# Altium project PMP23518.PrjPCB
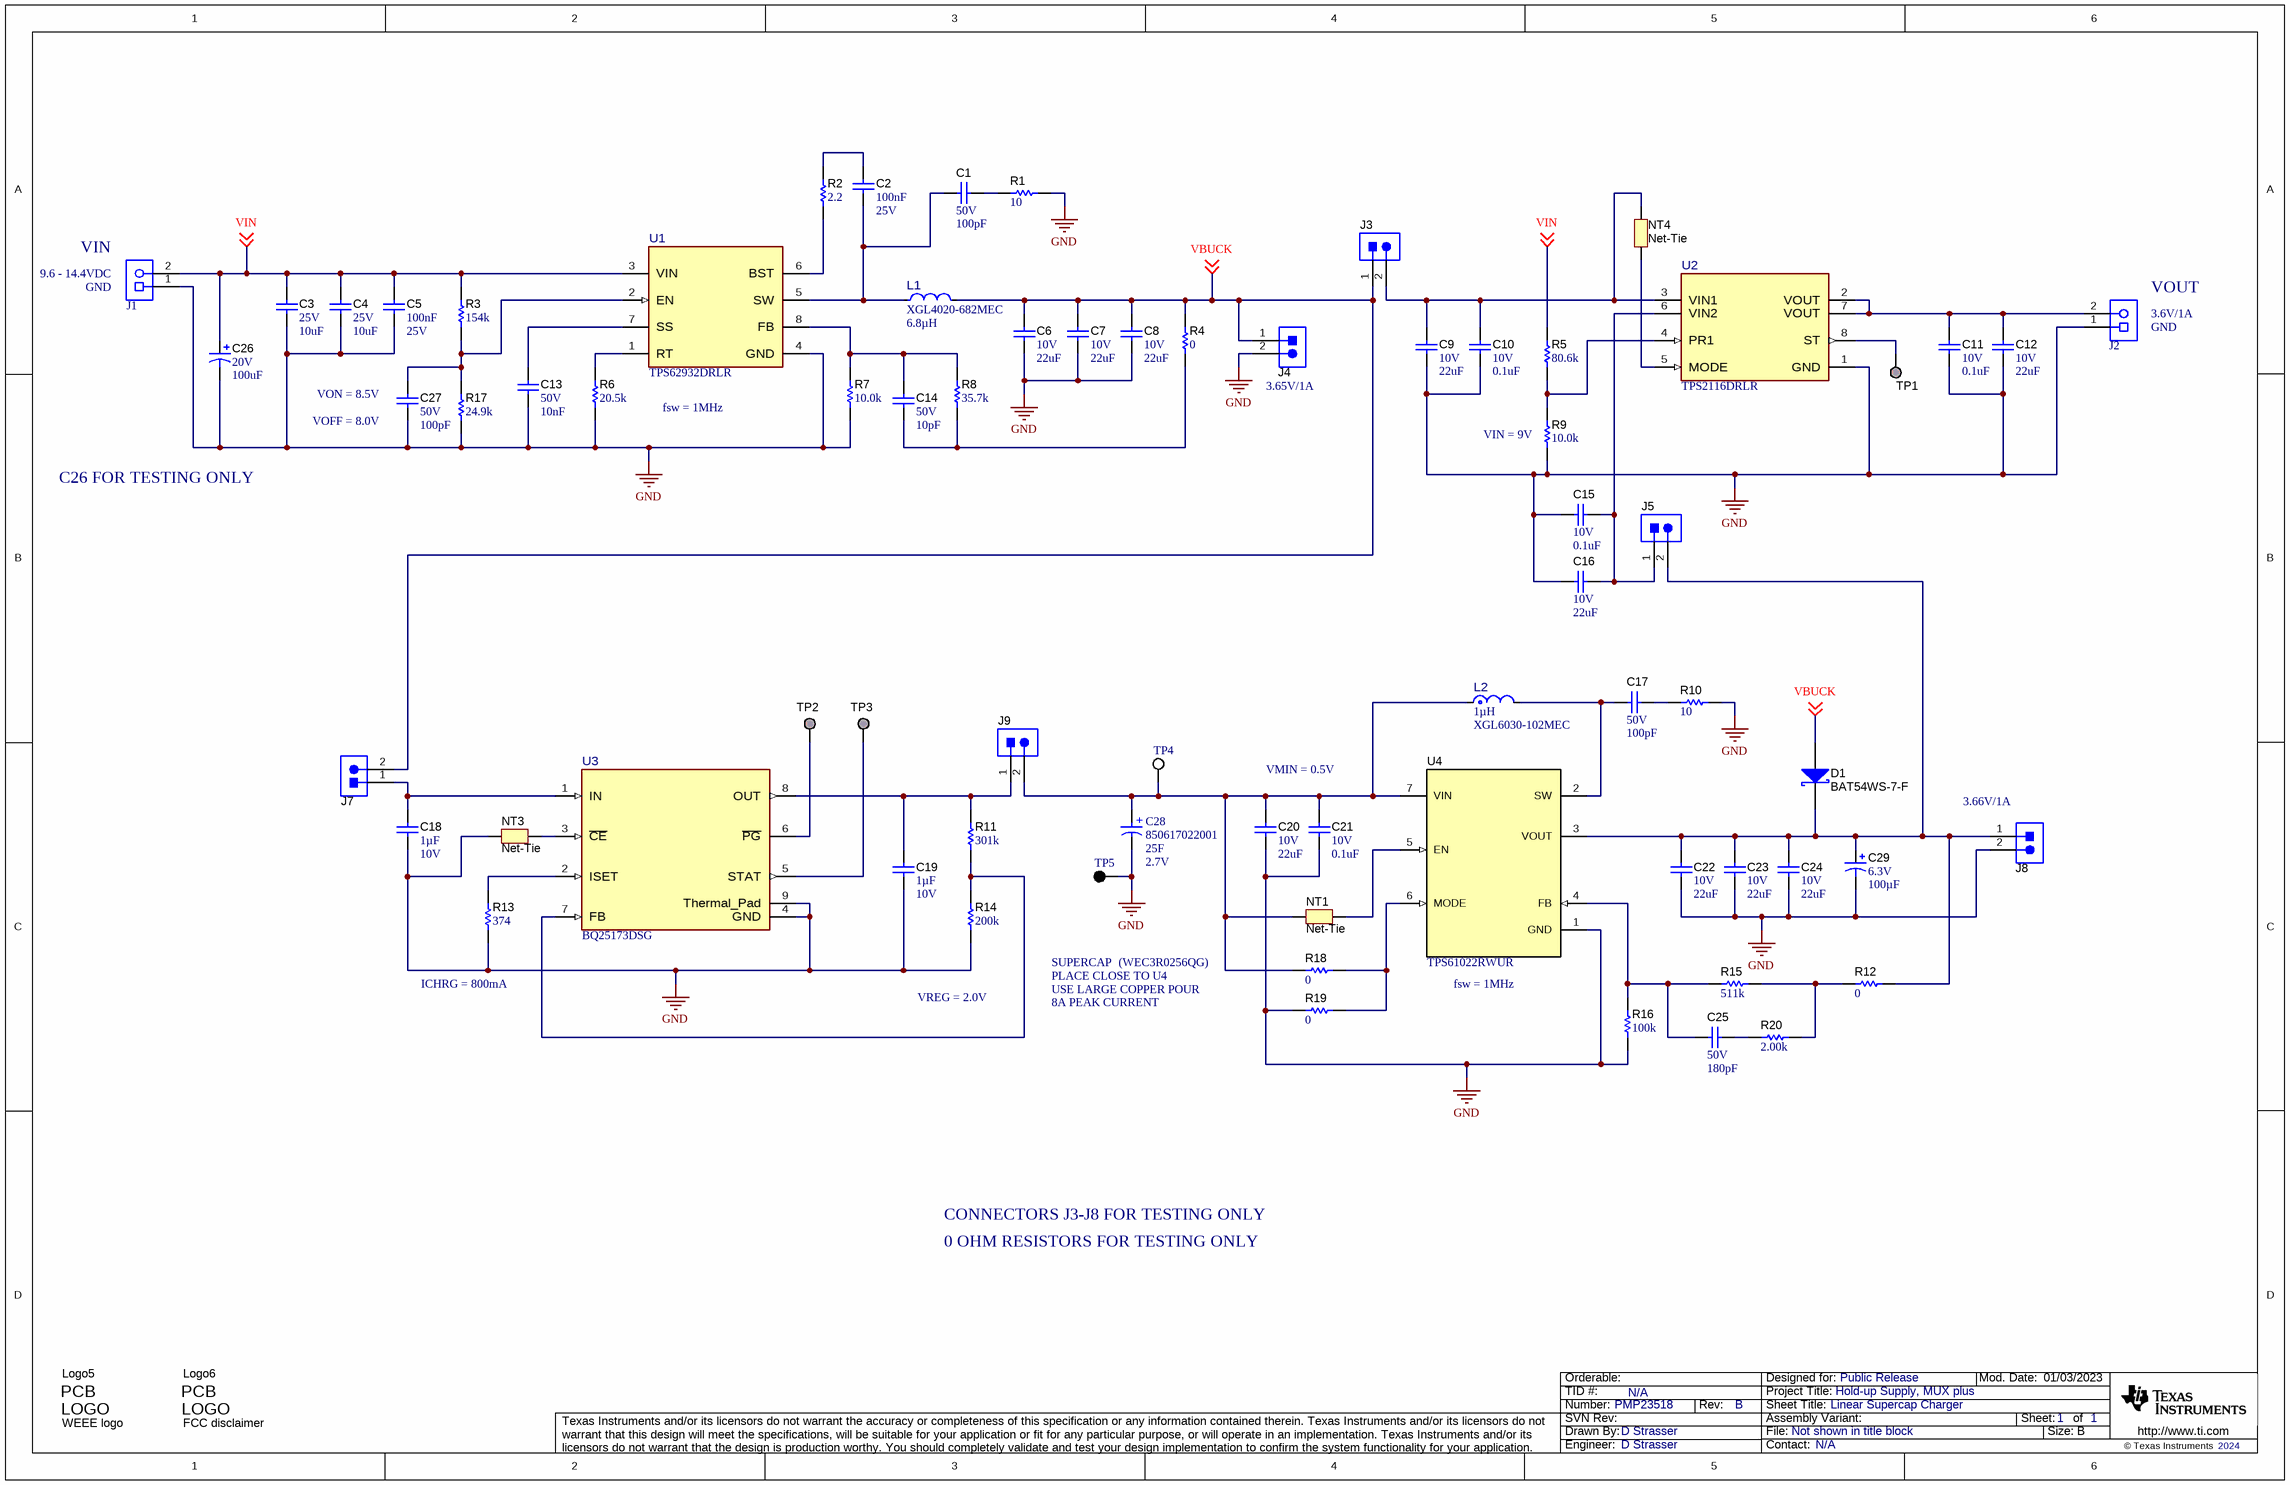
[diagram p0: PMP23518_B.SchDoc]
CopyrightYear: 2024; PCB_Layout: D Strasser; PCB_Rev: B; PRJ_Customer: Public Release; PRJ_Engineer: D Strasser; PRJ_Number: PMP23518; PRJ_Title: Hold-up Supply, MUX plus; SCH_Rev: B; TechSupport: N/A; TID: N/A
1 sheet, 74 parts. Net scope: global (net labels, ports and power ports of the same name join across sheets).
Board file: PMP23518_B.PcbDoc

## Sheet PMP23518_B.SchDoc: Linear Supercap Charger
size 431 x 279 mm; Date: Not shown in title block; ApprovedBy: Not shown in title block; CheckedBy: Not shown in title block; Author: Not shown in title block; CompanyName: Not shown in title block; DrawnBy: D Strasser; Engineer: Not shown in title block; Organization: Not shown in title block; Address1: Not shown in title block; Address2: Not shown in title block; Address3: Not shown in title block; Address4: Not shown in title block; DocumentNumber: 1; Revision: Use project parameter SCH_Rev; SheetNumber: 1; SheetTotal: 1; PageSetup: Record=PageOptions¦CenterHorizontal=True¦CenterVertical=True¦PrintScale=1.00¦XCorrection=1.00¦YCorrection=1.00¦PrintKind=0¦BorderSize=5000000¦LeftOffset=0¦BottomOffset=0¦Orientation=2¦PaperLength=1000¦PaperWidth=1000¦Scale=100¦PaperSource=15¦PrintQuality=600¦MediaType=1¦DitherType=10¦PaperKind=Letter¦PrintScaleMode=1

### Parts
C1  VDC_V: 50V  ValueDisplayed: 100pF  [0603]  (hidden comment: 885012006057)
C2  Cap_F: 100nF  VDC_V: 25V  [0603]  (hidden comment: 885012206071)
C3  VDC_V: 25V  ValueDisplayed: 10uF  [1206]  (hidden comment: 885012208069)
C4  VDC_V: 25V  ValueDisplayed: 10uF  [1206]  (hidden comment: 885012208069)
C5  Cap_F: 100nF  VDC_V: 25V  [0603]  (hidden comment: 885012206071)
C6  VDC_V: 10V  ValueDisplayed: 22uF  [0805_HV1]  (hidden comment: GRM21BR61A226ME44L)
C7  VDC_V: 10V  ValueDisplayed: 22uF  [0805_HV1]  (hidden comment: GRM21BR61A226ME44L)
C8  VDC_V: 10V  ValueDisplayed: 22uF  [0805_HV1]  (hidden comment: GRM21BR61A226ME44L)
C9  VDC_V: 10V  ValueDisplayed: 22uF  [0805_HV1]  (hidden comment: GRM21BR61A226ME44L)
C10  VDC_V: 10V  ValueDisplayed: 0.1uF  [0402]  (hidden comment: 885012105010)
C11  VDC_V: 10V  ValueDisplayed: 0.1uF  [0402]  (hidden comment: 885012105010)
C12  VDC_V: 10V  ValueDisplayed: 22uF  [0805_HV1]  (hidden comment: GRM21BR61A226ME44L)
C13  VDC_V: 50V  Cap_F: 10nF  [0603]  (hidden comment: 885012206089)
C14  VDC_V: 50V  ValueDisplayed: 10pF  [0402]  (hidden comment: 885012005055)
C15  VDC_V: 10V  ValueDisplayed: 0.1uF  [0402]  (hidden comment: 885012105010)
C16  VDC_V: 10V  ValueDisplayed: 22uF  [0805_HV1]  (hidden comment: GRM21BR61A226ME44L)
C17  VDC_V: 50V  ValueDisplayed: 100pF  [0603]  (hidden comment: 885012006057)
C18  Cap_F: 1µF  VDC_V: 10V  [0603]  (hidden comment: 885012206026)
C19  Cap_F: 1µF  VDC_V: 10V  [0603]  (hidden comment: 885012206026)
C20  VDC_V: 10V  ValueDisplayed: 22uF  [0805_HV1]  (hidden comment: GRM21BR61A226ME44L)
C21  VDC_V: 10V  ValueDisplayed: 0.1uF  [0402]  (hidden comment: 885012105010)
C22  VDC_V: 10V  ValueDisplayed: 22uF  [0805_HV1]  (hidden comment: GRM21BR61A226ME44L)
C23  VDC_V: 10V  ValueDisplayed: 22uF  [0805_HV1]  (hidden comment: GRM21BR61A226ME44L)
C24  VDC_V: 10V  ValueDisplayed: 22uF  [0805_HV1]  (hidden comment: GRM21BR61A226ME44L)
C25  VDC_V: 50V  ValueDisplayed: 180pF  [0402]  (hidden comment: GRM1555C1H181JA01D)
C26  VDC_V: 20V  ValueDisplayed: 100uF  [Panasonic_D3L]  (hidden comment: 20TQC100MYF)
C27  VDC_V: 50V  ValueDisplayed: 100pF  [0402]  (hidden comment: 885012005061)
C28  850617022001  Cap_F: 25F  Rated Voltage (DC): 2.7V  [WCAP-STSC_D16H25]
C29  VDC_V: 6.3V  ValueDisplayed: 100µF  [3528-20]  (hidden comment: 6TPE100MAZB)
D1  BAT54WS-7-F  [SOD-323]
J1  691214110002  [Wurth_691214110002]  (value not drawn)
J2  691214110002  [Wurth_691214110002]  (value not drawn)
J3  TSW-102-07-G-S  [TSW-102-07-G-S]  (value not drawn)
J4  TSW-102-07-G-S  [TSW-102-07-G-S]  (value not drawn)
J5  TSW-102-07-G-S  [TSW-102-07-G-S]  (value not drawn)
J7  TSW-102-07-G-S  [TSW-102-07-G-S]  (value not drawn)
J8  TSW-102-07-G-S  [TSW-102-07-G-S]  (value not drawn)
J9  TSW-102-07-G-S  [TSW-102-07-G-S]  (value not drawn)
L1  Ind_H: 6.8µH  [FP-XGL4020-682MEC_SMD2-MFG]  (hidden comment: XGL4020-682MEC)
L2  Ind_H: 1µH  [FP-XGL6030-102MEC_SMT2_6MM51_6MM71-MFG]  (hidden comment: XGL6030-102MEC)
Logo5  WEEE logo  [WEEE_Minimum]  (no BOM)
Logo6  FCC disclaimer  [FCC_disclaimer]  (no BOM)
NT1  Net-Tie  [Net-Tie_10mil]  (net tie, no BOM)
NT3  Net-Tie  [Net-Tie_10mil]  (net tie, no BOM)
NT4  Net-Tie  [Net-Tie_10mil]  (net tie, no BOM)
R1  ValueDisplayed: 10  [0603]  (hidden comment: CRCW060310R0JNEA)
R2  ValueDisplayed: 2.2  [0402]  (hidden comment: CRCW04022R20JNED)
R3  ValueDisplayed: 154k  [0402]  (hidden comment: CRCW0402154KFKED)
R4  ValueDisplayed: 0  [0402]  (hidden comment: CRCW04020000Z0ED)
R5  ValueDisplayed: 80.6k  [0402]  (hidden comment: CRCW040280K6FKED)
R6  ValueDisplayed: 20.5k  [0402]  (hidden comment: CRCW040220K5FKED)
R7  ValueDisplayed: 10.0k  [0402]  (hidden comment: CRCW040210K0FKED)
R8  ValueDisplayed: 35.7k  [0402]  (hidden comment: CRCW040235K7FKED)
R9  ValueDisplayed: 10.0k  [0402]  (hidden comment: CRCW040210K0FKED)
R10  ValueDisplayed: 10  [0603]  (hidden comment: CRCW060310R0JNEA)
R11  ValueDisplayed: 301k  [0402]  (hidden comment: CRCW0402301KFKED)
R12  ValueDisplayed: 0  [0402]  (hidden comment: CRCW04020000Z0ED)
R13  ValueDisplayed: 374  [0402]  (hidden comment: CRCW0402374RFKED)
R14  ValueDisplayed: 200k  [0402]  (hidden comment: CRCW0402200KFKED)
R15  ValueDisplayed: 511k  [0402]  (hidden comment: CRCW0402511KFKED)
R16  ValueDisplayed: 100k  [0402]  (hidden comment: CRCW0402100KFKED)
R17  ValueDisplayed: 24.9k  [0402]  (hidden comment: CRCW040224K9FKED)
R18  ValueDisplayed: 0  [0402]  (hidden comment: CRCW04020000Z0ED)
R19  ValueDisplayed: 0  [0402]  (hidden comment: CRCW04020000Z0ED)
R20  ValueDisplayed: 2.00k  [0402]  (hidden comment: CRCW04022K00FKED)
TP1  TP_SM_1MM  [TP_SM_1MM]  (value not drawn)  (no BOM)
TP2  TP_SM_1MM  [TP_SM_1MM]  (value not drawn)  (no BOM)
TP3  TP_SM_1MM  [TP_SM_1MM]  (value not drawn)  (no BOM)
TP4  5002  [Keystone5002]  (value not drawn)
TP5  5001  [Keystone5001]  (value not drawn)
U1  TPS62932DRLR  [DRL0008A-MFG]
U2  TPS2116DRLR  [DRL0008A-MFG]
U3  BQ25173DSG  [DSG0008A-MFG]
U4  TPS61022RWUR  [RWU0007A]

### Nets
GND: C3.1 C4.1 C5.1 C6.1 C7.1 C8.1 C9.1 C10.2 C11.2 C12.1 C13.1 C15.2 C16.2 C18.1 C19.1 C20.1 C21.2 C22.1 C23.1 C24.1 C26.2(-) C27.1 C28.2(N) C29.2(-) J1.1 J2.1 J4.2 J8.2 NT3.1 R1.2 R6.2 R7.2 R9.2 R10.2 R13.2 R14.2 R16.2 R17.2 R19.1 TP5.1 U1.4(GND) U2.1(GND) U3.4(GND) U3.9(Thermal_Pad) U4.1(GND)
VBUCK: C6.2 C7.2 C8.2 D1.2(A) J3.1 J4.1 J7.2 L1.2 R4.2 ; off-sheet VBUCK
VIN: C3.2 C4.2 C5.2 C26.1(+) J1.2 R3.1 R5.1 U1.3(VIN) ; off-sheet VIN
NetC1_1: C1.1 R1.1
NetC1_2: C1.2 C2.2 L1.1 U1.5(SW)
NetC2_1: C2.1 R2.2
NetC9_2: C9.2 C10.1 J3.2 NT4.2 U2.3(VIN1)
NetC11_1: C11.1 C12.2 J2.2 U2.2(VOUT) U2.7(VOUT)
NetC13_2: C13.2 U1.7(SS)
NetC14_1: C14.1 R4.1 R8.1
NetC14_2: C14.2 R7.1 R8.2 U1.8(FB)
NetC15_1: C15.1 C16.1 J5.1 U2.6(VIN2)
NetC17_1: C17.1 R10.1
NetC17_2: C17.2 L2.2 U4.2(SW)
NetC18_2: C18.2 J7.1 U3.1(IN)
NetC19_2: C19.2 J9.1 R11.1 U3.8(OUT)
NetC20_2: C20.2 C21.1 C28.1(P) J9.2 L2.1 NT1.1 R18.1 TP4.1 U4.7(VIN)
NetC22_2: C22.2 C23.2 C24.2 C29.1(+) D1.1(K) J5.2 J8.1 R12.2 U4.3(VOUT)
NetC25_1: C25.1 R20.1
NetC25_2: C25.2 R15.2 R16.1 U4.4(FB)
NetC27_2: C27.2 R3.2 R17.1 U1.2(EN)
NetNT1_2: NT1.2 U4.5(EN)
NetNT3_2: NT3.2 U3.3(~{CE})
NetNT4_1: NT4.1 U2.5(MODE)
NetR2_1: R2.1 U1.6(BST)
NetR5_2: R5.2 R9.1 U2.4(PR1)
NetR6_1: R6.1 U1.1(RT)
NetR11_2: R11.2 R14.1 U3.7(FB)
NetR12_1: R12.1 R15.1 R20.2
NetR13_1: R13.1 U3.2(ISET)
NetR18_2: R18.2 R19.2 U4.6(MODE)
NetTP1_1: TP1.1 U2.8(ST)
NetTP2_1: TP2.1 U3.6(~{PG})
NetTP3_1: TP3.1 U3.5(STAT)

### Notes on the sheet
- (near J1) 9.6 - 14.4VDC
- (near J1) GND
- (near J1) VIN
- (near J2) VOUT
- (near J2) 3.6V/1A
- (near J2) GND
- (near C27) VON = 8.5V
- (near C27) VOFF = 8.0V
- fsw = 1MHz
- (near J4) 3.65V/1A
- (near R9) VIN = 9V
- C26 FOR TESTING ONLY
- VMIN = 0.5V
- (near J8) 3.66V/1A
- SUPERCAP
- (WEC3R0256QG)
- (near R13) ICHRG = 800mA
- VREG = 2.0V
- PLACE CLOSE TO U4
- USE LARGE COPPER POUR
- 8A PEAK CURRENT
- (near U4) fsw = 1MHz
- CONNECTORS J3-J8 FOR TESTING ONLY
- 0 OHM RESISTORS FOR TESTING ONLY

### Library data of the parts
C1 C17 = CMP-0006822-4: CAP, CERM, 100 pF, 50 V, +/- 5%, C0G/NP0, 0603; Manufacturer: Wurth Elektronik; TaMin_C: -55°C; Polarized: N; SizeAreaWB_mm2: 4.68; Value1: Unknown; U/M: EA; Value: 100pF; TaMax_C: 125°C; SizeZ_mm: 1; SizeX_mm: 1.6; SizeY_mm: 0.8; SizeArea_mm2: 1.28; AEC Category: Q200
C2 C5 = CMP-0006832-5: CAP, CERM, 0.1 uF, 25 V, +/- 10%, X7R, 0603; Manufacturer: Wurth Elektronik; TaMin_C: -55°C; Polarized: N; SizeAreaWB_mm2: 4.68; Value1: Unknown; U/M: EA; Value: 0.1uF; TaMax_C: 125°C; SizeZ_mm: 1; SizeX_mm: 1.6; SizeY_mm: 0.8; SizeArea_mm2: 1.28; AEC Category: Q200
C3 C4 = CMP-0008574-2: CAP, CERM, 10 uF, 25 V, +/- 10%, X7R, 1206; Manufacturer: Wurth Elektronik; TaMin_C: -55°C; Polarized: N; SizeAreaWB_mm2: 10.92; Value1: Unknown; U/M: EA; Value: 10uF; TaMax_C: 125°C; SizeZ_mm: 1.35; SizeX_mm: 3.2; SizeY_mm: 1.6; SizeArea_mm2: 5.12; Cap_F: 10µF; AEC Category: Q200
C6-C9 C12 C16 C20 C22-C24 = CMP-0008286-2: CAP, CERM, 22 uF, 10 V, +/- 20%, X5R, 0805; Manufacturer: MuRata; TaMin_C: -55°C; Polarized: N; SizeAreaWB_mm2: 6.75; Value1: Unknown; U/M: EA; Value: 22uF; TaMax_C: 85°C; SizeZ_mm: 1.45; SizeX_mm: 2; SizeY_mm: 1.25; Cap_Case: 0805; SizeArea_mm2: 2.5; Cap_F: 22µF; AEC Category: Q200
C10 C11 C15 C21 = CMP-0006221-2: CAP, CERM, 0.1 uF, 10 V, +/- 20%, X5R, 0402; Manufacturer: Wurth Elektronik; TaMin_C: -55°C; Polarized: N; SizeAreaWB_mm2: 3; Value1: Unknown; U/M: EA; Value: 0.1uF; TaMax_C: 85°C; SizeZ_mm: 0.6; SizeX_mm: 1; SizeY_mm: 0.5; Cap_F: 100nF; AEC Category: Q200
C13 = CMP-0750039-1: CAP, CERM, 0.01 µF, 50 V,+/- 10%, X7R, 0603; Manufacturer: Wurth Elektronik; Polarized: N; AEC Category: Q200; TaMax_C: 125°C; SizeAreaWB_mm2: 4.68; Value: 0.01uF; SizeArea_mm2: 1.28; SizeY_mm: 0.8; SizeZ_mm: 1; ValueDisplayed: 0.01µF; SizeX_mm: 1.6; U/M: EA; TaMin_C: -55°C
C14 = CMP-0006215-2: CAP, CERM, 10 pF, 50 V, +/- 5%, C0G/NP0, 0402; Manufacturer: Wurth Elektronik; TaMin_C: -55°C; Polarized: N; SizeAreaWB_mm2: 3; Value1: Unknown; U/M: EA; Value: 10pF; TaMax_C: 125°C; SizeZ_mm: 0.6; SizeX_mm: 1; SizeY_mm: 0.5; AEC Category: Q200
C18 C19 = CMP-0064932-4: CAP, CERM, 1 uF, 10 V,+/- 10%, X7R, 0603; Manufacturer: Wurth Elektronik; TaMin_C: -55°C; Polarized: N; SizeAreaWB_mm2: 4.68; Value1: Unknown; U/M: EA; Value: 1uF; TaMax_C: 125°C; SizeZ_mm: 1; SizeX_mm: 1.6; SizeY_mm: 0.8; SizeArea_mm2: 1.28; AEC Category: Q200
C25 = CMP-0006425-2: CAP, CERM, 180 pF, 50 V, +/- 5%, C0G/NP0, 0402; Manufacturer: MuRata; TaMin_C: -55°C; Polarized: N; SizeAreaWB_mm2: 3; Value1: Unknown; U/M: EA; Value: 180pF; TaMax_C: 125°C; SizeZ_mm: 0.6; SizeX_mm: 1; SizeY_mm: 0.5; AEC Category: Q200
C26 = CMP-0012616-3: CAP, Tantalum Polymer, 100 uF, 20 V, +/- 20%, 0.055 ohm, 7.3x4.3mm SMD; Manufacturer: Panasonic; TaMin_C: -55°C; ESR_ohm: 55m; Polarized: Y; Value: 100uF; TaMax_C: 105°C; Cap_Case: 7.3x4.3x2.8mm; CompType: Capacitor; AEC Qualified: N; Cap_F: 100µF; IRMS_A: 1.7A; AEC Category: Q200
C27 = CMP-0006217-2: CAP, CERM, 100 pF, 50 V, +/- 5%, C0G/NP0, 0402; Manufacturer: Wurth Elektronik; TaMin_C: -55°C; Polarized: N; SizeAreaWB_mm2: 3; Value1: Unknown; U/M: EA; Value: 100pF; TaMax_C: 125°C; SizeZ_mm: 0.6; SizeX_mm: 1; SizeY_mm: 0.5; AEC Category: Q200
C28 = CMP-0102070-1: WCAP-STSC Supercapacitors (EDLCs), THT, D16 x H25mm, 25F, 2.7VDC; Manufacturer: Wurth Elektronik; Capacitance Tolerance: -10% / +30%; Discharge Current Max: 20.7A; Energy Density: 3.7Wh/kg; ESR (AC): 20m; ESR (DC): 25m; Leakage Current: 0.068mA; Pitch: 7.5mm; Power Density: 10.72kW/kg; Rated Discharge Current: 6A
C29 = CMP-0077420-3: CAP, Tantalum Polymer, 100 µF, 6.3 V,+/- 20%, 0.035 ohm, 3528 SMD; Manufacturer: Panasonic; TaMax_C: 105°C; TaMin_C: -55°C; CompType: Capacitor; AEC Qualified: N; Value: 100uF; AEC Category: Q200; Polarized: Y; ESR_ohm: 35m; IRMS_A: 1.4A
D1 = CMP-0028458-2: Diode, Schottky, 30 V, 0.2 A, SOD-323; Manufacturer: Diodes Inc.; SizeArea_mm2: 3.645; Green_Lifecycle: Active; Io_A: 200mA; TJmax_C: 125°C; Value2: 0.7V; Vf_V: 700mV; Green_REACh: Passed; Value1: 0.2A; Vr_V: 30V; AEC Category: Q101; SizeAreaWB_mm2: 8.695; SizeY_mm: 1.35; Value: 30V; SizeX_mm: 2.7; SizeZ_mm: 1
J1 J2 = CMP-0054825-2: Terminal Block, 3.5mm, 2x1, Tin, TH; Manufacturer: Wurth Elektronik; Pitch_mm: 3.5; CT: TRUE; CNHeader: FALSE; Voltage_V: 300V; Gender: Female; Cert_UL: Y; Row_Count: 1; Current_A: 10A
J3-J5 J7-J9 = CMP-0075405-3: Header, 100mil, 2x1, Gold, TH; Manufacturer: Samtec; Current_A: 6.3A; Green_Lifecycle: Active; Pitch_mm: 2.54; Cert_CSA: Y; Cert_VDE: N; Green_REACh: Passed; Row_Count: 1; Gender: Male; Voltage_V: 550V
L1 = CMP-0087878-1: Shielded Power Inductors; Manufacturer: Coilcraft; Symbol Name: SYM-XGL4020-682MEC; AEC Qualified: Yes; Material: Composite; Isat: 1.6A; SizeZ_mm: 2.1mm; AEC Grade: Grade 1; Irms: 4.2A; DCR_ohm: 70m
L2 = CMP-0001586-1: 1 µH Shielded Molded Inductor 18.1 A 4.9mOhm Max Nonstandard; Manufacturer: Coilcraft; AEC Grade: Grade 1; AEC Qualified: Yes; DCR_ohm: 4.9m; Irms: 18.1A; Isat: 7.5A; Material: Composite; SizeZ_mm: 3.1mm; Value: 1uH; Self Resonant Frequency: 42MHz; Shrouded: true; TaMax_C: +125°C; TaMin_C: -40°C; Test Frequency: 1MHz; Tolerance_%: 20%
Logo5 = CMP-0074769-3: Manufacturer: Texas Instruments; CompType: IC; AEC Category: Q200
Logo6 = CMP-0074847-1: FCC_disclaimer
NT1 NT3 NT4 = CMP-0078142-6: Single point connection between nets.
R1 R10 = CMP-0025703-4: RES, 10, 5%, 0.1 W, AEC-Q200 Grade 0, 0603; Manufacturer: Vishay-Dale; Power_W: 100mW; TempCo: 200 ppm/C; Value_Code: 10R0; Value: 10; EIA_Code: E24; SizeX_mm: 1.6; SizeY_mm: 0.8; SizeZ_mm: 1; Value2: 0.1W; SizeArea_mm2: 1.28; AEC Qualified: Y; VDC_V: 75V; AEC Category: Q200; AEC Grade: 0
R2 = CMP-0026898-3: RES, 2.2, 5%, 0.063 W, AEC-Q200 Grade 0, 0402; Manufacturer: Vishay-Dale; Power_W: 63mW; TempCo: 200 ppm/C; Value_Code: 2R20; Value: 2.2; EIA_Code: E24; SizeX_mm: 1; SizeY_mm: 0.5; SizeZ_mm: 0.6; Value2: 0.063W; AEC Qualified: Y; VDC_V: 50V; AEC Category: Q200; AEC Grade: 0
R3 = CMP-0026023-3: RES, 154 k, 1%, 0.063 W, AEC-Q200 Grade 0, 0402; Manufacturer: Vishay-Dale; Power_W: 63mW; TempCo: 100 ppm/C; Value: 154k; EIA_Code: E96; SizeX_mm: 1; SizeY_mm: 0.5; SizeZ_mm: 0.6; Value2: 0.063W; AEC Qualified: Y; VDC_V: 50V; AEC Category: Q200; AEC Grade: 0
R4 R12 R18 R19 = CMP-0026822-3: RES, 0, 5%, 0.063 W, AEC-Q200 Grade 0, 0402; Manufacturer: Vishay-Dale; Power_W: 63mW; TempCo: 200 ppm/C; Value_Code: 0000; Value: 0; EIA_Code: E24; SizeX_mm: 1; SizeY_mm: 0.5; SizeZ_mm: 0.6; Value2: 0.063W; AEC Qualified: Y; VDC_V: 50V; AEC Category: Q200
R5 = CMP-0026570-2: RES, 80.6 k, 1%, 0.063 W, AEC-Q200 Grade 0, 0402; Manufacturer: Vishay-Dale; Power_W: 63mW; TempCo: 100 ppm/C; Value_Code: 80k6; Value: 80.6k; EIA_Code: E96; SizeX_mm: 1; SizeY_mm: 0.5; SizeZ_mm: 0.6; Value2: 0.063W; AEC Qualified: Y; VDC_V: 50V; AEC Category: Q200; AEC Grade: 0
R6 = CMP-0026163-2: RES, 20.5 k, 1%, 0.063 W, AEC-Q200 Grade 0, 0402; Manufacturer: Vishay-Dale; Power_W: 63mW; TempCo: 100 ppm/C; Value_Code: 20k5; Value: 20.5k; EIA_Code: E96; SizeX_mm: 1; SizeY_mm: 0.5; SizeZ_mm: 0.6; Value2: 0.063W; AEC Qualified: Y; VDC_V: 50V; AEC Category: Q200; AEC Grade: 0
R7 R9 = CMP-0025958-3: RES, 10.0 k, 1%, 0.063 W, AEC-Q200 Grade 0, 0402; Manufacturer: Vishay-Dale; Power_W: 63mW; TempCo: 100 ppm/C; Value_Code: 10k0; Value: 10.0k; EIA_Code: E96; Res_ohm: 10k; SizeX_mm: 1; SizeY_mm: 0.5; SizeZ_mm: 0.6; Value2: 0.063W; AEC Qualified: Y; VDC_V: 50V; AEC Category: Q200; AEC Grade: 0
R8 = CMP-0026310-2: RES, 35.7 k, 1%, 0.063 W, AEC-Q200 Grade 0, 0402; Manufacturer: Vishay-Dale; Power_W: 63mW; TempCo: 100 ppm/C; Value_Code: 35k7; Value: 35.7k; EIA_Code: E96; SizeX_mm: 1; SizeY_mm: 0.5; SizeZ_mm: 0.6; Value2: 0.063W; AEC Qualified: Y; VDC_V: 50V; AEC Category: Q200; AEC Grade: 0
R11 = CMP-0026280-2: RES, 301 k, 1%, 0.063 W, AEC-Q200 Grade 0, 0402; Manufacturer: Vishay-Dale; Power_W: 63mW; TempCo: 100 ppm/C; Value: 301k; EIA_Code: E96; SizeX_mm: 1; SizeY_mm: 0.5; SizeZ_mm: 0.6; Value2: 0.063W; AEC Qualified: Y; VDC_V: 50V; AEC Category: Q200; AEC Grade: 0
R13 = CMP-0026318-2: RES, 374, 1%, 0.063 W, AEC-Q200 Grade 0, 0402; Manufacturer: Vishay-Dale; Power_W: 63mW; TempCo: 100 ppm/C; Value_Code: 374R; Value: 374; EIA_Code: E96; SizeX_mm: 1; SizeY_mm: 0.5; SizeZ_mm: 0.6; Value2: 0.063W; AEC Qualified: Y; VDC_V: 50V; AEC Category: Q200; AEC Grade: 0
R14 = CMP-0026158-2: RES, 200 k, 1%, 0.063 W, AEC-Q200 Grade 0, 0402; Manufacturer: Vishay-Dale; Power_W: 63mW; TempCo: 100 ppm/C; Value: 200k; EIA_Code: E96; SizeX_mm: 1; SizeY_mm: 0.5; SizeZ_mm: 0.6; Value2: 0.063W; AEC Qualified: Y; VDC_V: 50V; AEC Category: Q200; AEC Grade: 0
R15 = CMP-0026435-2: RES, 511 k, 1%, 0.063 W, AEC-Q200 Grade 0, 0402; Manufacturer: Vishay-Dale; Power_W: 63mW; TempCo: 100 ppm/C; Value: 511k; EIA_Code: E96; SizeX_mm: 1; SizeY_mm: 0.5; SizeZ_mm: 0.6; Value2: 0.063W; AEC Qualified: Y; VDC_V: 50V; AEC Category: Q200; AEC Grade: 0
R16 = CMP-0025950-3: RES, 100 k, 1%, 0.063 W, AEC-Q200 Grade 0, 0402; Manufacturer: Vishay-Dale; Power_W: 63mW; TempCo: 100 ppm/C; Value: 100k; EIA_Code: E96; SizeX_mm: 1; SizeY_mm: 0.5; SizeZ_mm: 0.6; Value2: 0.063W; AEC Qualified: Y; VDC_V: 50V; AEC Category: Q200; AEC Grade: 0
R17 = CMP-0026196-2: RES, 24.9 k, 1%, 0.063 W, AEC-Q200 Grade 0, 0402; Manufacturer: Vishay-Dale; Power_W: 63mW; TempCo: 100 ppm/C; Value_Code: 24k9; Value: 24.9k; EIA_Code: E96; SizeX_mm: 1; SizeY_mm: 0.5; SizeZ_mm: 0.6; Value2: 0.063W; AEC Qualified: Y; VDC_V: 50V; AEC Category: Q200; AEC Grade: 0
R20 = CMP-0026227-2: RES, 2.00 k, 1%, 0.063 W, AEC-Q200 Grade 0, 0402; Manufacturer: Vishay-Dale; Power_W: 63mW; TempCo: 100 ppm/C; Value_Code: 2k00; Value: 2.00k; EIA_Code: E96; Res_ohm: 2k; SizeX_mm: 1; SizeY_mm: 0.5; SizeZ_mm: 0.6; Value2: 0.063W; AEC Qualified: Y; VDC_V: 50V; AEC Category: Q200; AEC Grade: 0
TP1-TP3 = CMP-0003825-1: 1mm Test Point, SMT; Manufacturer: Any
TP4 = CMP-0055139-2: Test Point, Miniature, White, TH; Manufacturer: Keystone Electronics; ContactFinish: Silver; Green_REACh: Passed; CT: TRUE; Green_Lifecycle: Active; CNHeader: FALSE
TP5 = CMP-0055138-2: Test Point, Miniature, Black, TH; Manufacturer: Keystone Electronics; ContactFinish: Silver; CNHeader: FALSE; Green_Lifecycle: Active; Green_REACh: Passed; CT: TRUE
U1 = CMP-0094457-2: 3.8-V to 30-V, 2-A Synchronous Buck Converter in SOT583 Package; Manufacturer: Texas Instruments; SizeZ_mm: 0.6mm; Max Duty Cycle: 98%; Min Supply Voltage: 3.8V; Output Type: AdjustableProgrammable; Number Of Outputs: 1; AEC Qualified: No; AEC Category: Q200; Nominal Supply Current: 12uA; CompType: IC; Standoff Height: 0mm; TJmax_C: +150°C; Switching Frequency: 310-2100kHz; Max Supply Voltage: 30V; Output Voltage: 0.8-22V
U2 = CMP-0088593-2: 1.6 V to 5 V, 2.5-A Low IQ Power Mux With Manual and Automatic Switchover; Manufacturer: Texas Instruments; Max Supply Voltage: 5.5V; TaMax_C: +125°C; Output Voltage: 0-5.5V; CompType: IC; Min Supply Voltage: 1.6V; TaMin_C: -55°C; SizeZ_mm: 0.6mm; AEC Category: Q200; Nominal Supply Current: 0.5-1uA; Number Of Outputs: 1; Standoff Height: 0mm; AEC Qualified: No
U3 = CMP-0093602-1: 800-mA Linear Charger for 1- to 4-Cell Super Capacitor; Manufacturer: Texas Instruments; Min Supply Voltage: 3V; AEC Qualified: No; Output Voltage: 10.5V; Number Of Outputs: 1; Nominal Supply Current: 0.35-0.8uA; Number Of Cells: 4; Standoff Height: 0mm; SizeZ_mm: 0.8mm; TJmax_C: +125°C; Max Supply Voltage: 18V
U4 = CMP-0078852-3: 8-A Boost Converter with 0.5-V Ultra-Low Input Voltage, RWU0007A (VQFN-HR-7); Alternate PartNumber: TPS61022RWUT; Alternate Manufacturer: Texas Instruments; SizeAreaWB_mm2: 9; SizeZ_mm: 1; SizeX_mm: 2; SizeArea_mm2: 4; CompType: IC; AEC Qualified: N; AEC Category: Q200

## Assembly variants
001: not fitted C1 C17 D1 R1 R10 R18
